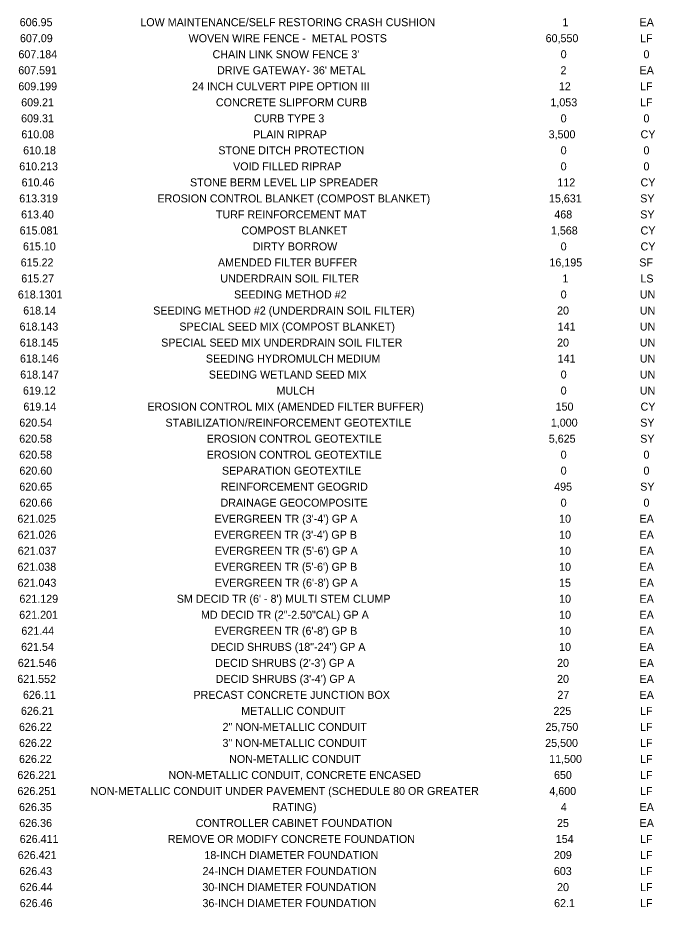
# Model space of a CAD drawing. Extents: x -18.7 to 5.6, y -2.7 to 5.1.
# Drawn here: x 0.03 to 0.812, y -1.562 to -0.468 of the extents above; entities that cross this region are included whole.
import ezdxf

# ---------------------------------------------------------------- set-up
doc = ezdxf.new("R2010")
doc.units = 0
doc.layers.add('ANNOTATION', color=7, linetype='Continuous')

msp = doc.modelspace()

# ---------------------------------------------------------------- texts
at = {"layer": 'ANNOTATION'}
for s, height, p in [('606.95', 0.00984, (0.0319, -0.4787)), ('LOW MAINTENANCE/SELF RESTORING CRASH CUSHION', 0.009843, (0.18, -0.4787)), ('1', 0.00984, (0.6984, -0.4787)), ('EA', 0.00984, (0.7931, -0.4787)), ('607.09', 0.00984, (0.0322, -0.4984)), ('WOVEN WIRE FENCE -  METAL POSTS', 0.009843, (0.2393, -0.4984)), ('60,550', 0.00984, (0.6777, -0.4984)), ('LF', 0.00984, (0.7937, -0.4984)), ('607.184', 0.00984, (0.0303, -0.5181)), ("CHAIN LINK SNOW FENCE 3'", 0.009843, (0.2687, -0.5181)), ('0', 0.00984, (0.6962, -0.5181)), ('0', 0.00984, (0.7979, -0.5181)), ('607.591', 0.00984, (0.0301, -0.5378)), ("DRIVE GATEWAY- 36' METAL", 0.009843, (0.2742, -0.5378)), ('2', 0.00984, (0.696, -0.5378)), ('EA', 0.00984, (0.7931, -0.5378)), ('609.199', 0.00984, (0.0302, -0.5575)), ('24 INCH CULVERT PIPE OPTION III', 0.009843, (0.2435, -0.5575)), ('12', 0.00984, (0.694, -0.5575)), ('LF', 0.00984, (0.7937, -0.5575)), ('609.21', 0.00984, (0.0337, -0.5772)), ('CONCRETE SLIPFORM CURB', 0.009843, (0.2728, -0.5772)), ('1,053', 0.00984, (0.6836, -0.5772)), ('LF', 0.00984, (0.7937, -0.5772)), ('609.31', 0.00984, (0.0336, -0.5969)), ('CURB TYPE 3', 0.009843, (0.3196, -0.5969)), ('0', 0.00984, (0.6962, -0.5969)), ('0', 0.00984, (0.7979, -0.5969)), ('610.08', 0.00984, (0.0339, -0.6165)), ('PLAIN RIPRAP', 0.009843, (0.3185, -0.6165)), ('3,500', 0.00984, (0.6814, -0.6165)), ('CY', 0.00984, (0.7943, -0.6165)), ('610.18', 0.00984, (0.0361, -0.6362)), ('STONE DITCH PROTECTION', 0.009843, (0.2758, -0.6362)), ('0', 0.00984, (0.6962, -0.6362)), ('0', 0.00984, (0.7979, -0.6362)), ('610.213', 0.00984, (0.0313, -0.6559)), ('VOID FILLED RIPRAP', 0.009843, (0.2939, -0.6559)), ('0', 0.00984, (0.6962, -0.6559)), ('0', 0.00984, (0.7979, -0.6559)), ('610.46', 0.00984, (0.0342, -0.6756)), ('STONE BERM LEVEL LIP SPREADER ', 0.009843, (0.241, -0.6756)), ('112', 0.00984, (0.6921, -0.6756)), ('CY', 0.00984, (0.7943, -0.6756)), ('613.319', 0.00984, (0.0313, -0.6953)), ('EROSION CONTROL BLANKET (COMPOST BLANKET)', 0.009843, (0.201, -0.6953)), ('15,631', 0.00984, (0.6818, -0.6953)), ('SY', 0.00984, (0.7939, -0.6953)), ('613.40', 0.00984, (0.0336, -0.715)), ('TURF REINFORCEMENT MAT', 0.009843, (0.2728, -0.715)), ('468', 0.00984, (0.6884, -0.715)), ('SY', 0.00984, (0.7939, -0.715)), ('615.081', 0.00984, (0.0318, -0.7347)), ('COMPOST BLANKET', 0.009843, (0.3041, -0.7347)), ('1,568', 0.00984, (0.6842, -0.7347)), ('CY', 0.00984, (0.7943, -0.7347)), ('615.10', 0.00984, (0.0359, -0.7543)), ('DIRTY BORROW', 0.009843, (0.318, -0.7543)), ('0', 0.00984, (0.6962, -0.7543)), ('CY', 0.00984, (0.7943, -0.7543)), ('615.22', 0.00984, (0.0331, -0.774)), ('AMENDED FILTER BUFFER', 0.009843, (0.2753, -0.774)), ('16,195', 0.00984, (0.6824, -0.774)), ('SF', 0.00984, (0.7927, -0.774)), ('615.27', 0.00984, (0.0338, -0.7937)), ('UNDERDRAIN SOIL FILTER', 0.009843, (0.2782, -0.7937)), ('1', 0.00984, (0.6984, -0.7937)), ('LS', 0.00984, (0.7941, -0.7937)), ('618.1301', 0.00984, (0.0296, -0.8134)), ('SEEDING METHOD #2', 0.009843, (0.2951, -0.8134)), ('0', 0.00984, (0.6962, -0.8134)), ('UN', 0.00984, (0.7934, -0.8134)), ('618.14', 0.00984, (0.0362, -0.8331)), ('SEEDING METHOD #2 (UNDERDRAIN SOIL FILTER)', 0.009843, (0.1958, -0.8331)), ('20', 0.00984, (0.6918, -0.8331)), ('UN', 0.00984, (0.7934, -0.8331)), ('618.143', 0.00984, (0.0317, -0.8528)), ('SPECIAL SEED MIX (COMPOST BLANKET)', 0.009843, (0.2279, -0.8528)), ('141', 0.00984, (0.6925, -0.8528)), ('UN', 0.00984, (0.7934, -0.8528)), ('618.145', 0.00984, (0.032, -0.8725)), ('SPECIAL SEED MIX UNDERDRAIN SOIL FILTER', 0.009843, (0.2056, -0.8725)), ('20', 0.00984, (0.6918, -0.8725)), ('UN', 0.00984, (0.7934, -0.8725)), ('618.146', 0.00984, (0.0322, -0.8921)), ('SEEDING HYDROMULCH MEDIUM', 0.009843, (0.2605, -0.8921)), ('141', 0.00984, (0.6925, -0.8921)), ('UN', 0.00984, (0.7934, -0.8921)), ('618.147', 0.00984, (0.0325, -0.9118)), ('SEEDING WETLAND SEED MIX', 0.009843, (0.2641, -0.9118)), ('0', 0.00984, (0.6962, -0.9118)), ('UN', 0.00984, (0.7934, -0.9118)), ('619.12', 0.00984, (0.0359, -0.9315)), ('MULCH', 0.00984, (0.3472, -0.9315)), ('0', 0.00984, (0.6962, -0.9315)), ('UN', 0.00984, (0.7934, -0.9315)), ('619.14', 0.00984, (0.0364, -0.9512)), ('EROSION CONTROL MIX (AMENDED FILTER BUFFER)', 0.009843, (0.1887, -0.9512)), ('150', 0.00984, (0.69, -0.9512)), ('CY', 0.00984, (0.7943, -0.9512)), ('620.54', 0.00984, (0.0314, -0.9709)), ('STABILIZATION/REINFORCEMENT GEOTEXTILE', 0.009843, (0.2109, -0.9709)), ('1,000', 0.00984, (0.6841, -0.9709)), ('SY', 0.00984, (0.7939, -0.9709)), ('620.58', 0.00984, (0.0313, -0.9906)), ('EROSION CONTROL GEOTEXTILE', 0.009843, (0.2615, -0.9906)), ('5,625', 0.00984, (0.6816, -0.9906)), ('SY', 0.00984, (0.7939, -0.9906)), ('620.58', 0.00984, (0.0313, -1.0103)), ('EROSION CONTROL GEOTEXTILE', 0.009843, (0.2615, -1.0103)), ('0', 0.00984, (0.6962, -1.0103)), ('0', 0.00984, (0.7979, -1.0103)), ('620.60', 0.00984, (0.0315, -1.0299)), ('SEPARATION GEOTEXTILE', 0.009843, (0.2802, -1.0299)), ('0', 0.00984, (0.6962, -1.0299)), ('0', 0.00984, (0.7979, -1.0299)), ('620.65', 0.00984, (0.0314, -1.0496)), ('REINFORCEMENT GEOGRID', 0.009843, (0.2788, -1.0496)), ('495', 0.00984, (0.6882, -1.0496)), ('SY', 0.00984, (0.7939, -1.0496)), ('620.66', 0.00984, (0.0317, -1.0693)), ('DRAINAGE GEOCOMPOSITE', 0.009843, (0.2785, -1.0693)), ('0', 0.00984, (0.6962, -1.0693)), ('0', 0.00984, (0.7979, -1.0693)), ('621.025', 0.00984, (0.029, -1.089)), ("EVERGREEN TR (3'-4') GP A", 0.009843, (0.2712, -1.089)), ('10', 0.00984, (0.6943, -1.089)), ('EA', 0.00984, (0.7931, -1.089)), ('621.026', 0.00984, (0.0293, -1.1087)), ("EVERGREEN TR (3'-4') GP B", 0.009843, (0.2706, -1.1087)), ('10', 0.00984, (0.6943, -1.1087)), ('EA', 0.00984, (0.7931, -1.1087)), ('621.037', 0.00984, (0.0295, -1.1284)), ("EVERGREEN TR (5'-6') GP A", 0.009843, (0.2715, -1.1284)), ('10', 0.00984, (0.6943, -1.1284)), ('EA', 0.00984, (0.7931, -1.1284)), ('621.038', 0.00984, (0.0291, -1.1481)), ("EVERGREEN TR (5'-6') GP B", 0.009843, (0.2709, -1.1481)), ('10', 0.00984, (0.6943, -1.1481)), ('EA', 0.00984, (0.7931, -1.1481)), ('621.043', 0.00984, (0.0293, -1.1677)), ("EVERGREEN TR (6'-8') GP A", 0.009843, (0.2716, -1.1677)), ('15', 0.00984, (0.6942, -1.1677)), ('EA', 0.00984, (0.7931, -1.1677)), ('621.129', 0.00984, (0.0315, -1.1874)), ("SM DECID TR (6' - 8') MULTI STEM CLUMP", 0.009843, (0.2248, -1.1874)), ('10', 0.00984, (0.6943, -1.1874)), ('EA', 0.00984, (0.7931, -1.1874)), ('621.201', 0.00984, (0.0313, -1.2071)), ('MD DECID TR (2"-2.50"CAL) GP A', 0.009843, (0.2545, -1.2071)), ('10', 0.00984, (0.6943, -1.2071)), ('EA', 0.00984, (0.7931, -1.2071)), ('621.44', 0.00984, (0.0339, -1.2268)), ("EVERGREEN TR (6'-8') GP B", 0.009843, (0.271, -1.2268)), ('10', 0.00984, (0.6943, -1.2268)), ('EA', 0.00984, (0.7931, -1.2268)), ('621.54', 0.00984, (0.0336, -1.2465)), ('DECID SHRUBS (18"-24") GP A', 0.009843, (0.2665, -1.2465)), ('10', 0.00984, (0.6943, -1.2465)), ('EA', 0.00984, (0.7931, -1.2465)), ('621.546', 0.00984, (0.0296, -1.2662)), ("DECID SHRUBS (2'-3') GP A", 0.009843, (0.272, -1.2662)), ('20', 0.00984, (0.6918, -1.2662)), ('EA', 0.00984, (0.7931, -1.2662)), ('621.552', 0.00984, (0.0289, -1.2859)), ("DECID SHRUBS (3'-4') GP A", 0.009843, (0.2725, -1.2859)), ('20', 0.00984, (0.6918, -1.2859)), ('EA', 0.00984, (0.7931, -1.2859)), ('626.11', 0.00984, (0.0359, -1.3055)), ('PRECAST CONCRETE JUNCTION BOX', 0.009843, (0.2452, -1.3055)), ('27', 0.00984, (0.6922, -1.3055)), ('EA', 0.00984, (0.7931, -1.3055)), ('626.21', 0.00984, (0.0334, -1.3252)), ('METALLIC CONDUIT', 0.009843, (0.3039, -1.3252)), ('225', 0.00984, (0.6873, -1.3252)), ('LF', 0.00984, (0.7937, -1.3252)), ('626.22', 0.00984, (0.031, -1.3449)), ('2" NON-METALLIC CONDUIT', 0.009843, (0.281, -1.3449)), ('25,750', 0.00984, (0.6776, -1.3449)), ('LF', 0.00984, (0.7937, -1.3449)), ('626.22', 0.00984, (0.031, -1.3646)), ('3" NON-METALLIC CONDUIT', 0.009843, (0.2809, -1.3646)), ('25,500', 0.00984, (0.6772, -1.3646)), ('LF', 0.00984, (0.7937, -1.3646)), ('626.22', 0.00984, (0.031, -1.3843)), ('NON-METALLIC CONDUIT', 0.009843, (0.2891, -1.3843)), ('11,500', 0.00984, (0.6821, -1.3843)), ('LF', 0.00984, (0.7937, -1.3843)), ('626.221', 0.00984, (0.029, -1.404)), ('NON-METALLIC CONDUIT, CONCRETE ENCASED', 0.009843, (0.2146, -1.404)), ('650', 0.00984, (0.688, -1.404)), ('LF', 0.00984, (0.7937, -1.404)), ('626.251', 0.00984, (0.0291, -1.4237)), ('NON-METALLIC CONDUIT UNDER PAVEMENT (SCHEDULE 80 OR GREATER ', 0.009843, (0.1189, -1.4237)), ('4,600', 0.00984, (0.6823, -1.4237)), ('LF', 0.00984, (0.7937, -1.4237)), ('626.35', 0.00984, (0.031, -1.4434)), ('RATING)', 0.00984, (0.3423, -1.4434)), ('4', 0.00984, (0.6964, -1.4434)), ('EA', 0.00984, (0.7931, -1.4434)), ('626.36', 0.00984, (0.0313, -1.463)), ('CONTROLLER CABINET FOUNDATION', 0.009843, (0.248, -1.463)), ('25', 0.00984, (0.6917, -1.463)), ('EA', 0.00984, (0.7931, -1.463)), ('626.411', 0.00984, (0.0319, -1.4827)), ('REMOVE OR MODIFY CONCRETE FOUNDATION', 0.009843, (0.2138, -1.4827)), ('154', 0.00984, (0.6902, -1.4827)), ('LF', 0.00984, (0.7937, -1.4827)), ('626.421', 0.00984, (0.0295, -1.5024)), ('18-INCH DIAMETER FOUNDATION', 0.009843, (0.2587, -1.5024)), ('209', 0.00984, (0.6879, -1.5024)), ('LF', 0.00984, (0.7937, -1.5024)), ('626.43', 0.00984, (0.0314, -1.5221)), ('24-INCH DIAMETER FOUNDATION', 0.009843, (0.2564, -1.5221)), ('603', 0.00984, (0.6878, -1.5221)), ('LF', 0.00984, (0.7937, -1.5221)), ('626.44', 0.00984, (0.0319, -1.5418)), ('30-INCH DIAMETER FOUNDATION', 0.009843, (0.2562, -1.5418)), ('20', 0.00984, (0.6918, -1.5418)), ('LF', 0.00984, (0.7937, -1.5418)), ('626.46', 0.00984, (0.0319, -1.5615)), ('36-INCH DIAMETER FOUNDATION', 0.009843, (0.2563, -1.5615)), ('62.1', 0.00984, (0.6881, -1.5615)), ('LF', 0.00984, (0.7937, -1.5615))]:
    msp.add_text(s, height=height, dxfattribs=at).set_placement(p)

doc.saveas('drawing.dxf')
